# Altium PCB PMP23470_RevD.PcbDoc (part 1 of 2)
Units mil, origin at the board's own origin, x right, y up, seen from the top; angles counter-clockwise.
Board outline 2000 x 2300 mil, 2 copper layers (Top Layer, Bottom Layer), stack 61.2 mil thick; 73 components, 36 nets, 176 pads, 81 vias.
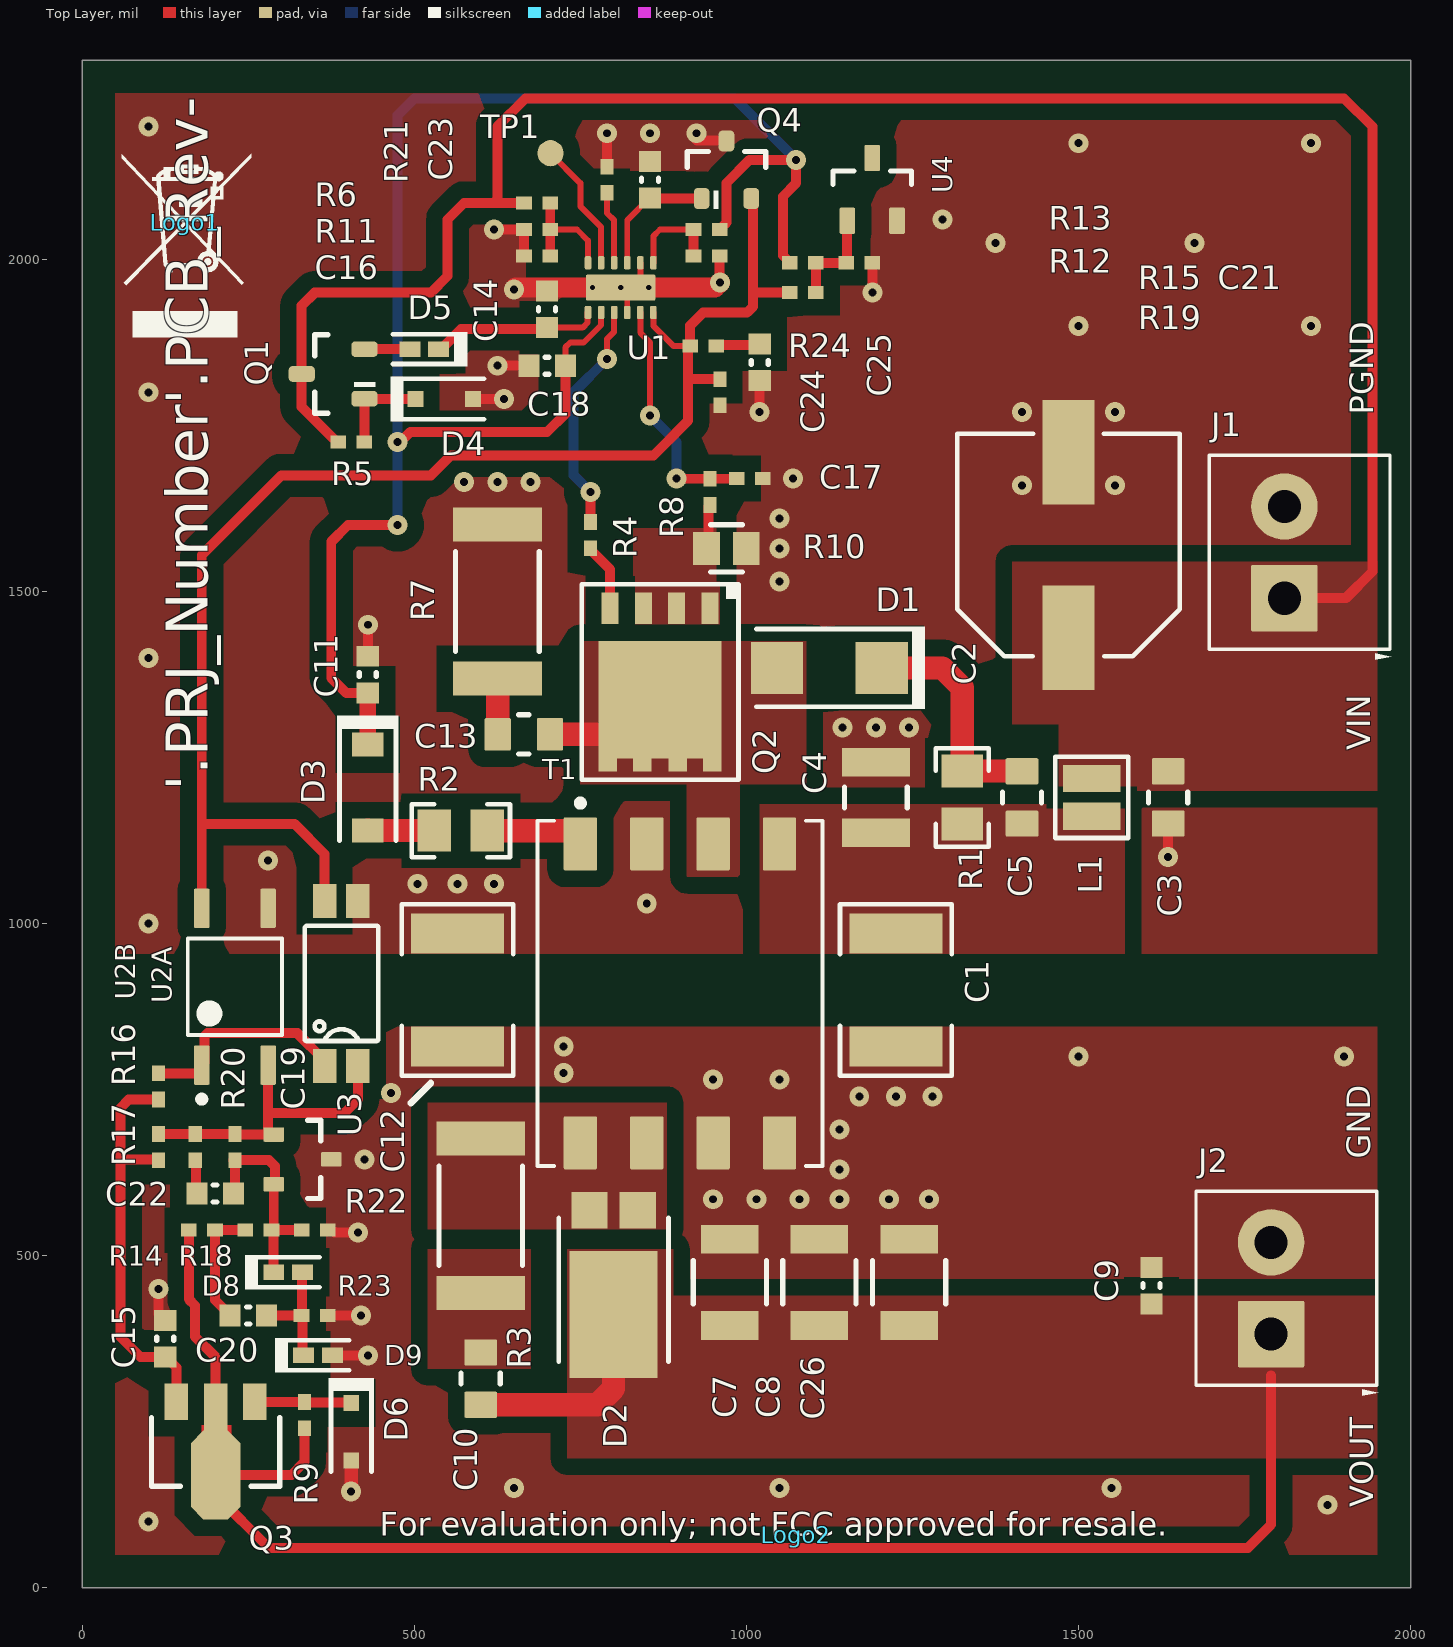
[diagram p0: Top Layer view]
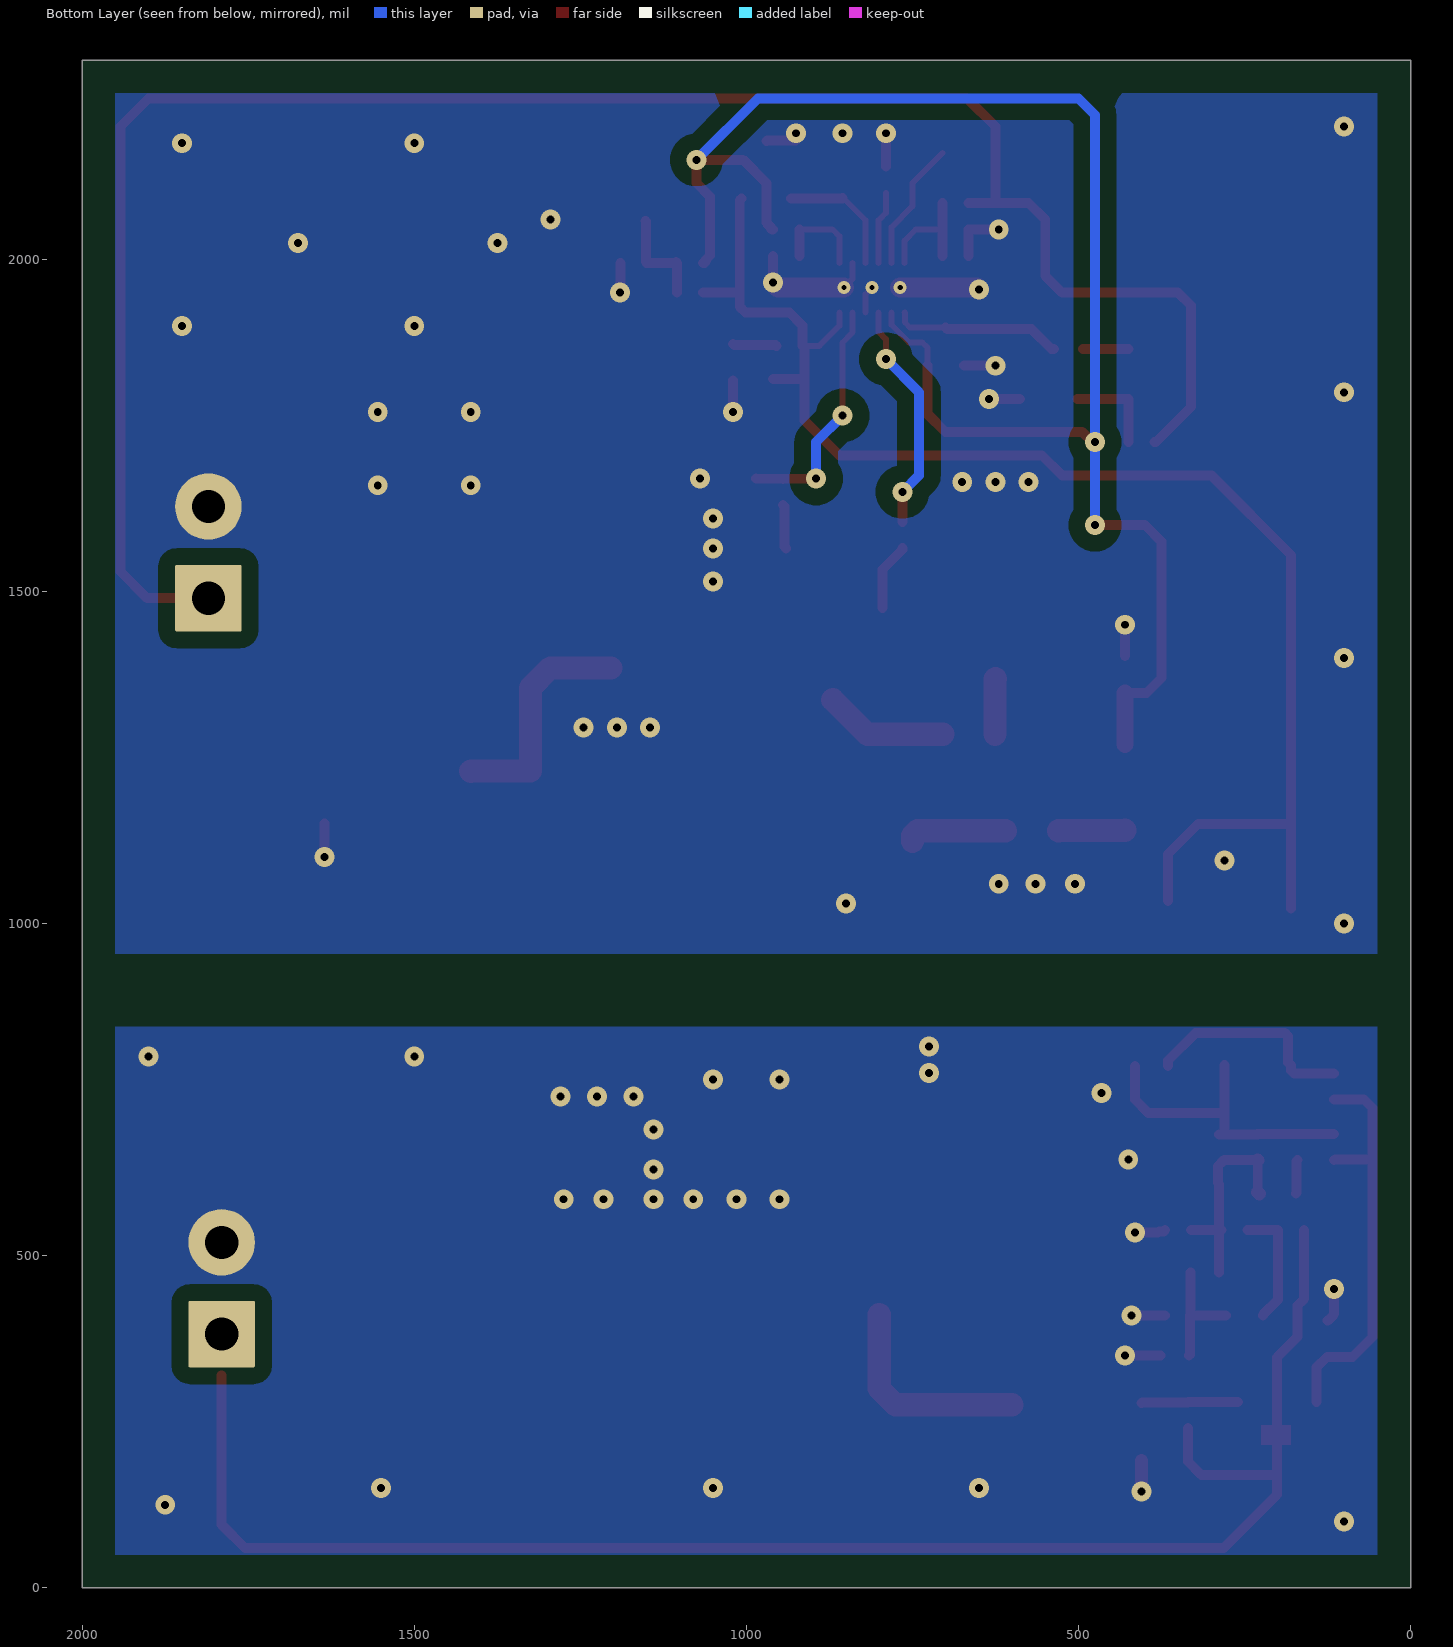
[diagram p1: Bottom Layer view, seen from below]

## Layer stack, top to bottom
Top Solder: solder mask 0.4, Solder Resist, Dk 3.5
Top Layer: signal copper 2.8
Dielectric1: core 55.6, FR-4, Dk 4.8
Bottom Layer: signal copper 2.8
Bottom Solder: solder mask 0.4, Solder Resist, Dk 3.5

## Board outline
0,0 2000,0 2000,2300 0,2300

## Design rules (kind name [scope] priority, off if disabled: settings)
AcuteAngle [All] p1: minimum=4.50000000000000E+0001 checktracksonly=FALSE
AssemblyTestPointUsage [All] p1: valid=2
BoardOutlineClearance BoardOutlineClearance_MountingHoles [OnCopper and InComponentClass('Mounting Holes')] p1: gap=40 ignorepadtopadclearanceinfootprint=FALSE
BoardOutlineClearance BoardOutlineClearance_Poly [OnCopper and IsPoly] p2: gap=25 ignorepadtopadclearanceinfootprint=FALSE
BoardOutlineClearance [OnCopper and Not InComponentClass('Logo') and not InComponentClass('FiducialMark') and not InRegion(1000,500,4000,800) and not InPoly] p3: gap=50 ignorepadtopadclearanceinfootprint=FALSE
Clearance Clearance_Keepouts [((IsTrack Or IsArc) And Not InPoly) And IsFree and IsKeepOut vs ((IsTrack Or IsArc) And Not InPoly) And IsFree and IsKeepOut] p1: gap=0 ignorepadtopadclearanceinfootprint=FALSE
Clearance Clearance_Poly [InPolygon] p2: gap=25 ignorepadtopadclearanceinfootprint=FALSE except(0: Arc-Hole Track-Hole SMDPad-Hole THPad-Hole Via-Hole Fill-Hole Poly-Hole Region-Hole Text-Hole)
Clearance Clearance_FiducialMark [IsKeepOut and InComponentClass('FiducialMark') vs IsPad and InComponentClass('FiducialMark')] p3: gap=0 ignorepadtopadclearanceinfootprint=FALSE
Clearance [All] p4: gap=7.87 ignorepadtopadclearanceinfootprint=FALSE except(0: Arc-Hole Track-Hole SMDPad-Hole THPad-Hole Via-Hole Fill-Hole Poly-Hole Region-Hole Text-Hole)
ComponentClearance ComponentClearance_MountingHoles_FiducialMarks [InComponentClass('Mounting Holes') vs InComponentClass('FiducialMark')] p1: gap=50 collisioncheckmode=3 verticalgap=10 showdistances=FALSE
ComponentClearance ComponentClearance_Shunt [InComponentClass('Header') vs InComponentClass('Shunt')] p2: gap=0 collisioncheckmode=3 verticalgap=0 showdistances=FALSE
ComponentClearance ComponentClearance_Logo [InComponentClass('Logo')] p3: gap=50 collisioncheckmode=3 verticalgap=10 showdistances=FALSE
ComponentClearance ComponentClearance_ScrewToNut [(HasFootprint('NY PMS 440 0025 PH')) vs (HasFootprint('Keystone_1902C'))] p4: gap=5 collisioncheckmode=3 verticalgap=10 showdistances=FALSE
ComponentClearance ComponentClearance_MountingHoles [InComponentClass('Mounting Holes')] p5: gap=250 collisioncheckmode=3 verticalgap=100000 showdistances=FALSE
ComponentClearance ComponentClearance_SmallPassives [HasFootprint('0201*') or HasFootprint('0402*') or HasFootprint('0508') or HasFootprint('0603*') or HasFootprint('0612') or HasFootprint('0805*') or HasFootprint('0815*') or HasFootprint('0830*') or HasFootprint('1206*') or HasFootprint('1210*') or HasFootprint('1808*') or HasFootprint('1812*') or HasFootprint('1825*') or HasFootprint('2010*') or HasFootprint('2220*') or HasFootprint('2225*') or HasFootprint('2512*') or HasFootprint('2728*') or HasFootprint('3518*') vs HasFootprint('0201*') or HasFootprint('0402*') or HasFootprint('0508') or HasFootprint('0603*') or HasFootprint('0612') or HasFootprint('0805*') or HasFootprint('0815*') or HasFootprint('0830*') or HasFootprint('1206*') or HasFootprint('1210*') or HasFootprint('1808*') or HasFootprint('1812*') or HasFootprint('1825*') or HasFootprint('2010*') or HasFootprint('2220*') or HasFootprint('2225*') or HasFootprint('2512*') or HasFootprint('2728*') or HasFootprint('3518*')] p6: gap=14.96 collisioncheckmode=3 verticalgap=10 showdistances=FALSE
ComponentClearance ComponentClearance_THtoSMT [IsThruComponent vs IsSMTComponent] p7: gap=40 collisioncheckmode=3 verticalgap=30 showdistances=FALSE
ComponentClearance ComponentClearance_THtoTH [IsThruComponent vs IsThruComponent] p8: gap=30 collisioncheckmode=3 verticalgap=30 showdistances=FALSE
ComponentClearance [All] p9: gap=30 collisioncheckmode=3 verticalgap=10 showdistances=FALSE
DiffPairsRouting [All] p1: maxlimit=100 minlimit=10 mostfreqgap=10 toplayer_minwidth=15 toplayer_maxwidth=15 toplayer_prefwidth=15 bottomlayer_minwidth=15 bottomlayer_maxwidth=15 bottomlayer_prefwidth=15 maxuncoupledlength=1000
FabricationTestPointUsage TestPointUsage [All] p1: valid=2 allowmultiple=FALSE
FabricationTestpoint Testpoint [All] p1: side=3 testpointundercomponent=TRUE minsize=40 maxsize=100 preferedsize=60 minholesize=0 maxholesize=40 preferedholesize=32 testpointgrid=1 allowsidetop=TRUE allowsidebottom=TRUE usegrid=TRUE gridtolerance=0.01
FanoutControl Fanout_LCC [IsLCC] p1: bgadir=Out bgaviamode=Centered fanoutstyle=Auto fanoutdirection=Alternating viagrid=1 // Fanout_LCC (Default Rule)
FanoutControl Fanout_BGA [IsBGA] p2: bgadir=Out bgaviamode=Centered fanoutstyle=Auto fanoutdirection=Alternating viagrid=1 // Fanout_BGA (Default Rule)
FanoutControl Fanout_Default [All] p4: bgadir=Out bgaviamode=Centered fanoutstyle=Auto fanoutdirection=Alternating viagrid=1 // Fanout_Default (Default Rule)
FanoutControl Fanout_Small [(CompPinCount < 5)] p5: bgadir=Out bgaviamode=Centered fanoutstyle=Auto fanoutdirection=OutThenIn viagrid=1 // Fanout_Small (Default Rule)
HoleSize [All] p1: absolutevalues=TRUE maxlimit=251 minlimit=7.87 maxpercent=80.000 minpercent=20.000
MinimumAnnularRing MinimumAnnularRing_ThermalPadVias [IsVia and InAnyComponent] p1: minimumring=5.91
MinimumAnnularRing [All] p2: minimumring=8
MinimumSolderMaskSliver MinimumSolderMaskSliver_Logo [InComponentClass('Logo') vs InComponentClass('Logo')] p1: minsoldermaskwidth=0.7
MinimumSolderMaskSliver [All] p2: minsoldermaskwidth=3.94
PlaneConnect [All] p1: planeconnectstyle=Relief reliefexpansion=10 reliefentries=4 reliefconductorwidth=10 reliefairgap=10
PolygonConnect [All] p1: connectstyle=Direct reliefconductorwidth=10 reliefentries=4 polygonreliefangle="90 Angle" airgapwidth=10
RoutingVias ThermalPadVias [IsVia and InAnyComponent] p1: holewidth=7.87 width=19.68 viastyle="Through Hole" minholewidth=7.87 minwidth=19.68 maxholewidth=12.99 maxwidth=23.62
RoutingVias [All] p2: holewidth=12 width=30 viastyle="Through Hole" minholewidth=7.87 minwidth=26 maxholewidth=40 maxwidth=65
SilkToBoardRegionClearance [Not ((IsComment or IsDesignator) And (Hide <> 'False')) and not InRegion(1000,500,4000,800)] p1:
SilkToSilkClearance SilkToSilkClearance_Pb-FreeLogo [(HasFootprint('Pb-Free_Overlay_Medium') OR HasFootprint('Pb-Free_Overlay_Small')) vs (HasFootprint('Pb-Free_Overlay_Medium') OR HasFootprint('Pb-Free_Overlay_Small'))] p1: silktosilkclearance=0
SilkToSilkClearance [All] p2: silktosilkclearance=4
SilkToSolderMaskClearance SilkToComponentPadClearance [(IsPad or IsFill or IsRegion) and InAnycomponent] p1: minsilkscreentomaskgap=5 clearancetoexposedcopper=TRUE
SilkToSolderMaskClearance "Silk to Solder Mask Opening" [All] p2: minsilkscreentomaskgap=4 clearancetoexposedcopper=FALSE
SolderMaskExpansion [All] p1: expansion=1.97 istentingtop=FALSE
Width [All] p1: maxlimit=100 minlimit=6 preferedwidth=10 checkconnectedcopper=TRUE
15 further rules are at their usual default settings.

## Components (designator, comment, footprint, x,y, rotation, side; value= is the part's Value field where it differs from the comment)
C1 "1812GC472KA1" 1812_HV 1225,900 r90 top value=4700pF
C2 "EEE-FK2A220P" SM_RADIAL_F 1485,1570 r90 top value=22uF
C3 "885012207128" 0805_HV1 1635,1190 r90 top value=0.1uF
C4 "C1210C225K1RAC7800" 1210_210L 1195,1190 r270 top value=2.2uF
C5 "885012207128" 0805_HV1 1415,1190 r270 top value=0.1uF
C7 "C1210C475K5RACAUTO" 1210_280 975,460 r270 top value=4.7uF
C8 "C1210C475K5RACAUTO" 1210_280 1110,460 r270 top value=4.7uF
C9 "C0603C104K5RACTU" 0603L 1610,455 r90 top value=0.1uF
C10 "GRM21A5C2E101JW01D" 0805_HV1 600,315 r270 top value=100pF
C11 "C0603C105K3RACTU" 0603L 430,1375 r270 top value=1uF
C12 "1812GC472KA1" 1812_HV 565,900 r90 top value=4700pF
C13 "GRM21A5C2E101JW01D" 0805_HV1 665,1285 r0 top value=100pF
C14 "C0603C104K5RACTU" 0603L 700,1925 r270 top value=0.1uF
C15 "C0603C105K3RACTU" 0603L 125,375 r270 top value=1uF
C16 "885012005044" 0402L 685,2005 r0 top value=47pF
C17 "GRM1555C1H121JA01D" 0402L 1005,1670 r180 top value=120pF
C18 "C0603C105K3RACTU" 0603L 700,1840 r0 top value=1uF
C19 "Table 1" 0402L 230.2,663.47 r90 top value=100pF
C20 "C1608X7R1H473K080AA" 0603L 250,410 r180 top value=0.047uF
C21 "885012205037" 0402L 1170,1995 r0 top value=0.1uF
C22 "Table 1" 0603L 200.2,593.47 r180 top value=0.01uF
C23 "C0603C104K5RACTU" 0603L 855,2120 r90 top value=0.1uF
C24 "885012005062" 0402L 960,1800 r270 top value=150pF
C25 "885012206070" 0603L 1020,1845 r90 top value=0.068uF
C26 "C1210C475K5RACAUTO" 1210_280 1245,460 r270 top value=4.7uF
D1 "ES2DA-13-F" SMA 1125,1385 r180 top value=200V
D2 "PDU620-13" POWERDI5 800,490 r270 top value=200V
D3 "1N4148W-7-F" SOD-123 430,1205 r270 top value=100V
D4 "MMSZ5250BS-7-F" SOD-323 545,1790 r0 top value=20V
D5 "BAS516,115" SOD-523 515,1865 r180 top value=100V
D6 "MMSZ5240BS-7-F" SOD-323 405,235 r270 top value=10V
D8 "BAS516,115" SOD-523 310,475 r0 top value=100V
D9 "BAS516,115" SOD-523 355,350 r0 top value=100V
J1 "ED555/2DS" TERM_BLK_ED555-2DS 1810,1490 r90 top
J2 "ED555/2DS" TERM_BLK_ED555-2DS 1790,382 r90 top
L1 "EPL2014-332MLB" EPL2014 1520,1190 r270 top value=3.3uH
Logo1 "WEEE logo" WEEE_Minimum 155,2055 r0 top
Logo2 "FCC disclaimer" FCC_disclaimer 1075,80 r0 top
Q1 "ZVN3310FTA" SOT-23 377.76,1827.6 r180 top value=100V
Q2 "BSC520N15NS3 G" PG-TDSON-8 870,1363.78 r270 top value=150V
Q3 "FCX493TA" SOT-89-3 200.94,205.2 r270 top value="100 V"
Q4 "FMMT718TA" SOT-23L 970,2135 r90 top value="20 V"
R1 "CRCW080539K0JNEA" 0805_HV 1325,1190 r90 top value=39k
R2 "ERJ-6GEYJ200V" 0805_HV 570,1140 r0 top value=20
R3 "CRCW251251R0JNEG" 2512 600,560 r270 top value=51
R4 "CRCW04024R70JNED" 0402L 765,1585 r90 top value=4.7
R5 "CRCW0402100KFKED" 0402L 405,1725 r0 top value=100k
R6 "CRCW0402150KFKED" 0402L 685,2085 r0 top value=150k
R7 "CRCW251251R0JNEG" 2512 625,1485 r90 top value=51
R8 "CRCW04021K00FKED" 0402L 945,1650 r90 top value=1.00k
R9 "CRCW040210K0FKED" 0402L 335,260 r270 top value=10.0k
R10 "WSL0805R0250FEA" WSL0805 970,1565 r0 top value=0.025
R11 "CRCW04026K19FKED" 0402L 685,2045 r180 top value=6.19k
R12 "CRCW04020000Z0ED" 0402L 940,2005 r180 top value=0
R13 "CRCW04020000Z0ED" 0402L 940,2045 r180 top value=0
R14 "CRCW040210R0FKED" 0402L 180.2,538.47 r0 top value=10.0
R15 "CRCW04021K00FKED" 0402L 1085,1995 r0 top value=1.00k
R16 "CRCW04022K00FKED" 0402L 115,755 r90 top value=2.00k
R17 "CRCW04024K99FKED" 0402L 115.2,663.47 r90 top value=4.99k
R18 "CRCW040230K1FKED" 0402L 265.2,538.47 r0 top value=30.1k
R19 "CRCW04022K49FKED" 0402L 1085,1950 r180 top value=2.49k
R20 "Table 1" 0402L 170.2,663.47 r270 top value=30.1k
R21 "CRCW040228K0FKED" 0402L 790,2120 r90 top value=28.0k
R22 "CRCW04023K48FKED" 0402L 350.2,538.47 r0 top value=3.48k
R23 "CRCW0402100KFKED" 0402L 350,410 r0 top value=100k
R24 "CRCW04021K00FKED" 0402L 935,1870 r0 top value=1.00k
T1 "ZF2955-AE" FP-ZF2955-AE_SMT_XFRMR_13MM2_10MM9-MFG 900,895 r90 top
TP1 "TP_SM_1MM" TP_SM_1MM 705,2160 r0 top
U1 "LM51561DSSR" DSS0012B 810.79,1957.6 r90 top
U2A "TCMT1107" SOP-4 390,910 r90 top
U2B "ISOM8110DFG" DFG0004A-MFG 230,905 r90 top value=80V
U3 "TL431LIAIDBZR" DBZ0003A_L 331.69,645 r0 top
U4 "LM4040D50IDBZR" DBZ0003A_N 1189.45,2105.5 r90 top

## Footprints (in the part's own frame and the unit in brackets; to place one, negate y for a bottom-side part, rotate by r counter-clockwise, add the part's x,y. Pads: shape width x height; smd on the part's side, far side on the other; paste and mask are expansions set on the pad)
0402L [mm] "0402 from SM-752 data"
  rect 0.6x0.5 smd: 1(-0.5,0) 2(0.5,0)
  body extent -0.55,-0.3 0.55,0.3, height 0.6
0603L [mm] "0603 from SM-752 data"
  rect 0.8x0.85 smd: 1(-0.7,0) 2(0.7,0)
  silkscreen extent -0.07,-0.33 0.07,0.33, body extent -0.87,-0.47 0.87,0.47, height 1
0805_HV [mil] "0805 with 30mil clearance between pads"
  rect 50x63 smd: 1(-40,0) 2(40,0)
  silkscreen extent -74,-40 74,40, body extent -43,-29 43,29, height 57
0805_HV1 [mm] "Custom footprint based on analyzing multiple manufacturer recommendations"
  rrect10% 1x1.25 smd: 1(-1,0) 2(1,0)
  silkscreen extent -0.2,-0.75 0.2,0.75, body extent -1.1,-0.72 1.1,0.73, height 1.45
1210_210L [mm] "1210"
  rect 1.1x2.6 smd: 1(-1.35,0) 2(1.35,0)
  silkscreen extent -0.4,-1.2 0.4,1.2, body extent -1.7,-1.35 1.7,1.35, height 2.1
1210_280 [mm] "SMD, 2-Leads, Body 3.6x2.8mm, Height 2.8mm"
  rect 1.1x2.2 smd: 1(-1.65,0) 2(1.65,0)
  silkscreen extent -0.84,-1.4 0.84,1.4, body extent -1.8,-1.4 1.8,1.4, height 2.8
1812_HV [mil] "PRG recommended land pattern"
  rect 60x140 smd: 1(-85,0) 2(85,0)
  silkscreen extent -129,-84 129,84, body extent -94,-67 94,67, height 53
2512 [mm] "Chip Resistor, Body 6.3x3.2mm, IPC Medium Density"
  rect 1.3x3.4 smd: 1(-2.95,0) 2(2.95,0)
  silkscreen extent -1.9,-1.6 1.9,1.6, body extent -3.22,-1.67 3.22,1.67, height 0.71
DBZ0003A_L [mm] "SOT23, 3-Leads, Body 2.9x1.3mm, Pitch 0.95mm, Lead Span 2.4mm, IPC High Density"
  rrect18% 0.8x0.55 smd: 1(-1.1,0.95) 2(-1.1,-0.95) 3(1.1,0)
  silkscreen extent 0.2,-1.5 0.7,1.5, body extent -1.26,-1.46 1.26,1.46, height 0.98
DBZ0003A_N [mm] "SOT23, 3-Leads, Body 2.9x1.3mm, Pitch 0.95mm, Lead Span 2.4mm, IPC Medium Density"
  rrect17% 1x0.6 smd: 1(-1.2,0.95) 2(-1.2,-0.95) 3(1.2,0)
  silkscreen extent 0.2,-1.5 0.7,1.5, body extent -1.26,-1.46 1.26,1.46, height 0.98
DFG0004A-MFG [mm]
  rrect17% 1.5x0.6 smd paste+0 mask+0: 1(-3,1.27) 2(-3,-1.27) 3(3,-1.27) 4(3,1.27)
  silkscreen extent -4.42,-1.81 1.85,1.81, body extent -3.85,-2.05 3.85,2.05, height 0.25
DSS0012B [mm] "WSON-10"
  rrect40% 0.5x0.25 smd: 1(-0.95,1.25) 2(-0.95,0.75) 3(-0.95,0.25) 4(-0.95,-0.25) 5(-0.95,-0.75) 6(-0.95,-1.25) 7(0.95,-1.25) 8(0.95,-0.75) 9(0.95,-0.25) 10(0.95,0.25) 11(0.95,0.75) 12(0.95,1.25)
  rrect11% 1x2.65 smd paste-0.5: 13(0,0)
  body extent -1,-1.5 1,1.5, height 0.81
EPL2014 [mm] "Coilcraft recommended land pattern.  Document 583-2, rev 1/12/09"
  rect 1.045x2.2 smd: 1(-0.723,0) 2(0.723,0)
  silkscreen extent -1.55,-1.4 1.55,1.4, body extent -1.1,-1.1 1.1,1.1, height 1.45
FCC_disclaimer [mil]
FP-ZF2955-AE_SMT_XFRMR_13MM2_10MM9-MFG [mm]
  rrect8% 2.03x1.27 smd paste+0 mask+0: 1(5.715,3.81) 2(5.715,1.27) 3(5.715,-1.27) 4(5.715,-3.81) 5(-5.715,-3.81) 6(-5.715,-1.27) 7(-5.715,1.27) 8(-5.715,3.81)
  silkscreen extent -6.6,-5.45 7.4,5.45, body extent -6.83,-5.55 6.83,5.55, height 0.25
PG-TDSON-8 [mm] "Infineon recommended land pattern"
  rect 1.2x0.65 smd: 1(-2.825,1.905) 2(-2.825,0.635) 3(-2.825,-0.635) 4(-2.825,-1.905)
  rect 0.5x0.7 smd: 5(3.175,-2) 6(3.175,-0.675) 7(3.175,0.675) 8(3.175,2)
  rect 4.5x4.7 smd paste-2.25: 9(0.675,0)
  silkscreen extent -3.74,-3 3.74,3, body extent -3.18,-2.89 3.18,2.9, height 1.1
POWERDI5 [mm] "Diodes Inc recommended land pattern, ap02001.pdf rev 60"
  rect 1.4x1.39 smd: 1(-1.991,0.92) 2(-1.991,-0.92)
  rect 4.86x3.36 smd: 3(1.991,0)
  silkscreen extent -1.7,-2.1 3.8,2.1, body extent -2.27,-2.03 4.33,2.03, height 1.17
SM_RADIAL_F [mm] "8 x 10.2mm:  Panasonic F"
  rect 4x2 smd: 1(-3.55,0) 2(3.55,0)
  silkscreen extent -4.25,-4.25 4.25,4.25, body extent -4.25,-4.25 4.25,4.25, height 10.5
SMA [mm] "Molded Diode, 2-Leads, Body 4.3x2.6mm, IPC Medium Density, based on OnSemi component dimensions and land pattern"
  rect 2x2 smd: 1(-2,0) 2(2,0)
  silkscreen extent -3.66,-1.57 2.79,1.57, body extent -2.6,-1.3 2.6,1.3, height 2.42
SOD-123 [mm] "On Semi recommended land pattern"
  rect 0.915x1.22 smd: 1(-1.637,0) 2(1.637,0)
  silkscreen extent -2.74,-1.17 2.03,1.17, body extent -1.93,-0.9 1.93,0.9, height 1.35
SOD-323 [mm] "NXP recommended land pattern"
  rect 0.6x0.6 smd paste-0.05: 1(-1.1,0) 2(1.1,0)
  silkscreen extent -2.06,-0.86 1.53,0.86, body extent -1.3,-0.67 1.3,0.68, height 1.1
SOD-523 [mm] "NXP Semiconductor recommended land pattern, nominal STEP model"
  rect 0.8x0.6 smd paste-0.05: 1(-0.55,0) 2(0.55,0)
  silkscreen extent -1.65,-0.66 1.2,0.66, body extent -0.8,-0.4 0.8,0.4, height 0.72
SOP-4 [mm] "Vishay Half Pitch Mini-Flat Package"
  rect 1.3x0.9 smd: 1(-3.15,0.635) 2(-3.15,-0.635) 3(3.15,-0.635) 4(3.15,0.635)
  silkscreen extent -2.2,-1.41 2.2,1.39, body extent -3.5,-1.4 3.5,1.4, height 2.12
SOT-23 [mm] "SOT23, 3-Leads, Body 2.9x1.3mm, Pitch 0.95mm, Lead Span 2.5mm, IPC Medium Density"
  rrect50% 1x0.6 smd: 1(-1.2,0.95) 2(-1.2,-0.95) 3(1.2,0)
  silkscreen extent -1.63,-1.5 0.7,1.5, body extent -1.16,-1.45 1.21,1.45, height 1
SOT-23L [mm] "SOT23, 3-Leads, Body 2.9x1.3mm, Pitch 0.95mm, Lead Span 2.5mm, IPC High Density"
  rrect50% 0.8x0.6 smd: 1(-1.1,0.95) 2(-1.1,-0.95) 3(1.1,0)
  silkscreen extent -1.5,-1.5 0.7,1.5, body extent -1.16,-1.45 1.21,1.45, height 1
SOT-89-3 [mm] "SOT, 3-Leads, Body 4.6 x 2.6 mm, Pitch 1.5mm"
  rect 1.4x0.9 smd: 1(-1.9,1.5) 3(-1.9,-1.5)
  rect 1.8x0.9 smd: 2(-1.7,0)
  oct 3.4x1.9 smd: 4(0.9,0)
  silkscreen extent -1.3,-2.45 1.33,2.45, body extent -2.42,-2.28 1.83,2.32, height 1.62
TERM_BLK_ED555-2DS [mil]
  rrect4% 100x100 hole 50: 1(0,0)
  round 100 hole 50: 2(138,0)
  silkscreen extent -93,-161 215,113, body extent -69,-150 207,106, height 323
TP_SM_1MM [mm] "1mm Test Point, SMT"
  round 1 smd paste-0.5: 1(0,0)
WEEE_Minimum [mil] "WEEElie bin"
  silkscreen extent -95,-172 99,104
WSL0805 [mm] "Vishay"
  rect 1.02x1.27 smd: 1(-0.76,0) 2(0.76,0)
  silkscreen extent -0.6,-0.9 0.6,0.9, body extent -1.14,-0.76 1.14,0.76, height 0.59

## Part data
C1 C12: library part CMP-0009294-2, "CAP, CERM, 4700 pF, 2000 V, +/- 10%, X7R, 1812", Cap_Case=1812, Manufacturer=AVX, Supplier Part Number 1=581-1812GC472KA11A, TempCo=X7R, Tolerance_%=10%, Value1=Unknown, Value2=2000V, ValueDisplayed=4700pF
C2: library part CMP-0011202-2, "CAP, AL, 22 uF, 100 V, +/- 20%, 1.3 ohm, AEC-Q200 Grade 2, SMD", Cap_Case=F, Manufacturer=Panasonic, Supplier Part Number 1=PCE3845CT-ND, Tolerance_%=20%, Value1="1.3 ohm", Value2=100V, ValueDisplayed=22uF
C3 C5: library part CMP-0750058-1, "CAP, CERM, 0.1 µF, 100 V,+/- 10%, X7R, 0805", Cap_Case=0805, Manufacturer="Wurth Elektronik", TempCo=X7R, Tolerance_%=10%, Value2=100V, ValueDisplayed=0.1µF
C4: library part CMP-0009084-2, "CAP, CERM, 2.2 uF, 100 V, +/- 10%, X7R, 1210", Cap_Case=1210, Manufacturer=Kemet, Supplier Part Number 1=399-5511-2-ND, TempCo=X7R, Tolerance_%=10%, Value1=Unknown, Value2=100V, ValueDisplayed=2.2uF
C7 C8 C26: library part CMP-0079604-1, "CAP, CERM, 4.7 µF, 50 V,+/- 10%, X7R, AEC-Q200 Grade 1, 1210", Cap_Case=1210, Manufacturer=Kemet, Supplier Part Number 1=399-7049-1-ND, TempCo=X7R, Tolerance_%=10%, Value2=50V, ValueDisplayed=4.7µF
C9 C14 C23: library part CMP-0006861-4, "CAP, CERM, 0.1 uF, 50 V, +/- 10%, X7R, 0603", Cap_Case=0603, Manufacturer=Kemet, Supplier Part Number 1=399-5089-1-ND, TempCo=X7R, Tolerance_%=10%, Value1=Unknown, Value2=50V, ValueDisplayed=0.1uF
C10 C13: library part CMP-0008236-2, "CAP, CERM, 100 pF, 250 V, +/- 5%, C0G/NP0, 0805", Cap_Case=0805, Manufacturer=MuRata, Supplier Part Number 1=490-5542-1-ND, TempCo=C0G/NP0, Tolerance_%=5%, Value1=Unknown, Value2=250V, ValueDisplayed=100pF
C11 C15 C18: library part CMP-0006867-4, "CAP, CERM, 1 uF, 25 V, +/- 10%, X7R, 0603", Cap_Case=0603, Manufacturer=Kemet, Supplier Part Number 1=399-7376-1-ND, TempCo=X7R, Tolerance_%=10%, Value1=Unknown, Value2=25V, ValueDisplayed=1uF
C16: library part CMP-0006214-2, "CAP, CERM, 47 pF, 50 V, +/- 5%, C0G/NP0, 0402", Cap_Case=0402, Manufacturer="Wurth Elektronik", Supplier Part Number 1=732-7459-1-ND, TempCo=C0G/NP0, Tolerance_%=5%, Value1=Unknown, Value2=50V, ValueDisplayed=47pF
C17: library part CMP-0006417-2, "CAP, CERM, 120 pF, 50 V, +/- 5%, C0G/NP0, 0402", Cap_Case=0402, Manufacturer=MuRata, Supplier Part Number 1=490-1292-1-ND, TempCo=C0G/NP0, Tolerance_%=5%, Value1=Unknown, Value2=50V, ValueDisplayed=120pF
C19: library part CMP-0006217-2, "CAP, CERM, 100 pF, 50 V, +/- 5%, C0G/NP0, 0402", Cap_Case=0402, Manufacturer="Wurth Elektronik", PartNumber=885012005061, Supplier Part Number 1=732-7475-1-ND, TempCo=C0G/NP0, Tolerance_%=5%, Value1=Unknown, Value2=50V, ValueDisplayed=100pF
C20: library part CMP-0007049-4, "CAP, CERM, 0.047 uF, 50 V, +/- 10%, X7R, 0603", Cap_Case=0603, Manufacturer=TDK, Supplier Part Number 1=445-1313-1-ND, TempCo=X7R, Tolerance_%=10%, Value1="0.049007 ohm", Value2=50V, ValueDisplayed=0.047uF
C21: library part CMP-0006228-2, "CAP, CERM, 0.1 uF, 16 V, +/- 10%, X7R, 0402", Cap_Case=0402, Manufacturer="Wurth Elektronik", Supplier Part Number 1=732-7532-1-ND, TempCo=X7R, Tolerance_%=10%, Value1=Unknown, Value2=16V, ValueDisplayed=0.1uF
C22: library part CMP-0750039-1, "CAP, CERM, 0.01 µF, 50 V,+/- 10%, X7R, 0603", Cap_Case=0603, Manufacturer="Wurth Elektronik", PartNumber=885012206089, TempCo=X7R, Tolerance_%=10%, Value2=50V, ValueDisplayed=0.01µF
C24: library part CMP-0064913-2, "CAP, CERM, 150 pF, 50 V,+/- 5%, C0G/NP0, 0402", Cap_Case=0402, Manufacturer="Wurth Elektronik", Supplier Part Number 1=732-7476-1-ND, TempCo=C0G/NP0, Tolerance_%=5%, Value1=Unknown, Value2=50V, ValueDisplayed=150pF
C25: library part CMP-0750069-1, "CAP, CERM, 0.068 µF, 25 V,+/- 10%, X7R, 0603", Cap_Case=0603, Manufacturer="Wurth Elektronik", TempCo=X7R, Tolerance_%=10%, Value2=25V, ValueDisplayed=0.068µF
D1: library part CMP-0076892-2, "Diode, Superfast Rectifier, 200 V, 2 A, SMA", Manufacturer="Diodes Inc.", Value1=2A, Value2=0.92V
D2: library part CMP-0077019-2, "Diode, Ultrafast, 200 V, 6 A, PowerDI5", Manufacturer="Diodes Inc.", Value1=6A, Value2=0.94V
D3: library part CMP-0029001-2, "Diode, Ultrafast, 100 V, 0.15 A, SOD-123", Manufacturer="Diodes Inc.", Value1=0.15A, Value2=1.25V
D4: library part CMP-0005836-4, "Diode, Zener, 20 V, 200 mW, SOD-323", Manufacturer="Diodes Inc.", Power_W=200mW, Value1=0.2W
D5 D8 D9: library part CMP-0076979-3, "Diode, Switching, 100 V, 0.25 A, SOD-523", Manufacturer=Nexperia, Value1=0.25A, Value2=1.25V
D6: library part CMP-0005829-3, "Diode, Zener, 10 V, 200 mW, SOD-323", Manufacturer="Diodes Inc.", Power_W=200mW, Value1=0.2W
J1 J2: library part CMP-0074913-1, "Terminal Block, 3.5mm Pitch, 2x1, TH", Color=Grey, Current_A=6A, Manufacturer="On-Shore Technology", Supplier Part Number 1=ED1514-ND, Voltage_V=150V
L1: library part CMP-0060326-1, "Inductor, Shielded, Ferrite, 3.3 uH, 1.1 A, 0.15 ohm, SMD", Manufacturer=Coilcraft, Value1="0.15 ohm", Value2=1.1A, ValueDisplayed=3.3uH
Logo1: library part CMP-0074769-4, Manufacturer="Texas Instruments"
Logo2: library part CMP-0074847-1, "FCC_disclaimer"
Q1: library part CMP-0001039-3, "MOSFET, N-CH, 100 V, 0.1 A, SOT-23", Alternate Manufacturer=None, Manufacturer="Diodes Inc.", Supplier Part Number 1=ZVN3310FCT-ND
Q2: library part CMP-0001049-2, "MOSFET, N-CH, 150 V, 21 A, PG-TDSON-8", Alternate Manufacturer=None, Manufacturer="Infineon Technologies", Supplier Part Number 1="BSC520N15NS3 GCT-ND", Value2="8.7 nC"
Q3: library part CMP-0000415-2, "Transistor, NPN, 100 V, 1 A, SOT-89", Manufacturer="Diodes Inc.", Supplier Part Number 1=FCX493CT-ND, Value1="1 A", Value2=300
Q4: library part CMP-0000330-2, "Transistor, PNP, 20 V, 1.5 A, SOT-23", Manufacturer="Diodes Inc.", Supplier Part Number 1=FMMT718CT-ND, Value1="1.5 A", Value2=6
R1: library part CMP-0020536-3, "RES, 39 k, 5%, 0.125 W, AEC-Q200 Grade 0, 0805", Manufacturer=Vishay-Dale, Power_W=125mW, Supplier Part Number 1=541-39KACT-ND, TempCo="200 ppm/C", Tolerance_%=5%, Value2=0.125W, Value_Code=39k0, ValueDisplayed=39k
R2: library part CMP-0020668-3, "RES, 20, 5%, 0.125 W, AEC-Q200 Grade 0, 0805", Manufacturer=Panasonic, Power_W=125mW, Supplier Part Number 1=P20ACT-ND, TempCo="200 ppm/C", Tolerance_%=5%, Value2=0.125W, Value_Code=20R0, ValueDisplayed=20
R3 R7: library part CMP-0015978-3, "RES, 51, 5%, 1 W, AEC-Q200 Grade 0, 2512", Manufacturer=Vishay-Dale, Power_W=1W, Supplier Part Number 1=541-51XCT-ND, TempCo="200 ppm/C", Tolerance_%=5%, Value_Code=51R0, ValueDisplayed=51
R4: "RES, 4.7, 5%, 0.063 W, 0402", Manufacturer=Vishay-Dale, Power_W=0.063, Supplier Part Number 1=541-4.7JCT-ND, TempCo="200 ppm/C", Tolerance_%=5, Value1=5%, Value2=0.063W, Value_Code=4R70, ValueDisplayed=4.7
R5 R23: library part CMP-0025950-3, "RES, 100 k, 1%, 0.063 W, AEC-Q200 Grade 0, 0402", Manufacturer=Vishay-Dale, Power_W=63mW, Supplier Part Number 1=541-100KLCT-ND, TempCo="100 ppm/C", Tolerance_%=1%, Value2=0.063W, Value_Code=100k
R6: library part CMP-0026021-3, "RES, 150 k, 1%, 0.063 W, AEC-Q200 Grade 0, 0402", Manufacturer=Vishay-Dale, Power_W=63mW, Supplier Part Number 1=541-150KLCT-ND, TempCo="100 ppm/C", Tolerance_%=1%, Value2=0.063W, Value_Code=150k
R8 R15 R24: library part CMP-0026071-3, "RES, 1.00 k, 1%, 0.063 W, AEC-Q200 Grade 0, 0402", Manufacturer=Vishay-Dale, Power_W=63mW, Supplier Part Number 1=541-1.00KLCT-ND, TempCo="100 ppm/C", Tolerance_%=1%, Value2=0.063W, Value_Code=1k00, ValueDisplayed=1.00k
R9: library part CMP-0025958-3, "RES, 10.0 k, 1%, 0.063 W, AEC-Q200 Grade 0, 0402", Manufacturer=Vishay-Dale, Power_W=63mW, Supplier Part Number 1=541-10.0KLCT-ND, TempCo="100 ppm/C", Tolerance_%=1%, Value2=0.063W, Value_Code=10k0, ValueDisplayed=10.0k
R10: library part CMP-0021981-2, "RES, 0.025, 1%, 0.25 W, 0805", Manufacturer=Vishay-Dale, Power_W=250mW, Supplier Part Number 1=WSLB-.015CT-ND, TempCo="75 ppm/C", Tolerance_%=1%, Value2=0.25W, Value_Code=R025, ValueDisplayed=0.025
R11: library part CMP-0026513-2, "RES, 6.19 k, 1%, 0.063 W, AEC-Q200 Grade 0, 0402", Manufacturer=Vishay-Dale, Power_W=63mW, Supplier Part Number 1=541-6.19KLCT-ND, TempCo="100 ppm/C", Tolerance_%=1%, Value2=0.063W, Value_Code=6k19, ValueDisplayed=6.19k
R12 R13: library part CMP-0026822-3, "RES, 0, 5%, 0.063 W, AEC-Q200 Grade 0, 0402", Manufacturer=Vishay-Dale, Power_W=63mW, Supplier Part Number 1=541-0.0JCT-ND, TempCo="200 ppm/C", Tolerance_%=5%, Value2=0.063W, Value_Code=0000, ValueDisplayed=0
R14: library part CMP-0025963-3, "RES, 10.0, 1%, 0.063 W, AEC-Q200 Grade 0, 0402", Manufacturer=Vishay-Dale, Power_W=63mW, Supplier Part Number 1=541-10.0LCT-ND, TempCo="100 ppm/C", Tolerance_%=1%, Value2=0.063W, Value_Code=10R0, ValueDisplayed=10.0
R16: library part CMP-0026227-2, "RES, 2.00 k, 1%, 0.063 W, AEC-Q200 Grade 0, 0402", Manufacturer=Vishay-Dale, Power_W=63mW, Supplier Part Number 1=541-2.00KLCT-ND, TempCo="100 ppm/C", Tolerance_%=1%, Value2=0.063W, Value_Code=2k00, ValueDisplayed=2.00k
R17: library part CMP-0026414-2, "RES, 4.99 k, 1%, 0.063 W, AEC-Q200 Grade 0, 0402", Manufacturer=Vishay-Dale, Power_W=63mW, Supplier Part Number 1=541-4.99KLCT-ND, TempCo="100 ppm/C", Tolerance_%=1%, Value2=0.063W, Value_Code=4k99, ValueDisplayed=4.99k
R18: library part CMP-0026284-2, "RES, 30.1 k, 1%, 0.063 W, AEC-Q200 Grade 0, 0402", Manufacturer=Vishay-Dale, Power_W=63mW, Supplier Part Number 1=541-30.1KLCT-ND, TempCo="100 ppm/C", Tolerance_%=1%, Value2=0.063W, Value_Code=30k1, ValueDisplayed=30.1k
R19: library part CMP-0026237-2, "RES, 2.49 k, 1%, 0.063 W, AEC-Q200 Grade 0, 0402", Manufacturer=Vishay-Dale, Power_W=63mW, Supplier Part Number 1=541-2.49KLCT-ND, TempCo="100 ppm/C", Tolerance_%=1%, Value2=0.063W, Value_Code=2k49, ValueDisplayed=2.49k
R20: library part CMP-0026284-2, "RES, 30.1 k, 1%, 0.063 W, AEC-Q200 Grade 0, 0402", Manufacturer=Vishay-Dale, PartNumber=CRCW040230K1FKED, Power_W=63mW, Supplier Part Number 1=541-30.1KLCT-ND, TempCo="100 ppm/C", Tolerance_%=1%, Value2=0.063W, Value_Code=30k1, ValueDisplayed=30.1k
R21: library part CMP-0026219-2, "RES, 28.0 k, 1%, 0.063 W, AEC-Q200 Grade 0, 0402", Manufacturer=Vishay-Dale, Power_W=63mW, Supplier Part Number 1=541-28.0KLCT-ND, TempCo="100 ppm/C", Tolerance_%=1%, Value2=0.063W, Value_Code=28k0, ValueDisplayed=28.0k
R22: library part CMP-0026335-2, "RES, 3.48 k, 1%, 0.063 W, AEC-Q200 Grade 0, 0402", Manufacturer=Vishay-Dale, Power_W=63mW, Supplier Part Number 1=541-3.48KLCT-ND, TempCo="100 ppm/C", Tolerance_%=1%, Value2=0.063W, Value_Code=3k48, ValueDisplayed=3.48k
T1: library part CMP-0121891-1, "Flyback Transformer, EP7 8pin SMD 40-57Vin, 750kHz, Output 24V/0.7A, 11.6V/0.02A, Turns Ratio 1:1:0.5", Manufacturer=Coilcraft, Operating Temperature Range=to, Voltage_Isolation_Vrms=1500Vrms
TP1: library part CMP-0003825-1, "1mm Test Point, SMT", Manufacturer=Any
U1: library part CMP-0860748-1, "2.2-MHz Wide VIN 65-V Non-synchronous Boost/SEPIC/Flyback Controller with Dual Random Spread Spectrum, DSS0012B (WSON-12)", Alternate Manufacturer="Texas Instruments", Alternate PartNumber=LM51561DSST
U2A: library part CMP-0006166-3, "Optocoupler, 3.75 kV, 80-160% CTR, SMT", Manufacturer=Vishay-Semiconductor, Supplier Part Number 1=TCMT1107CT-ND, Voltage_Isolation_Vrms=3.75kV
